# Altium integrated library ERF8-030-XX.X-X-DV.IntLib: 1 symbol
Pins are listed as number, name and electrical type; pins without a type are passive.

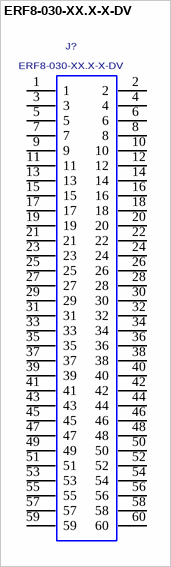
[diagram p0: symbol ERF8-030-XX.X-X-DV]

## ERF8-030-XX.X-X-DV
designator J?
0.8mm Edge Rate Socket Assembly, Double Vertical Row, 30 Positions Per Row.; MANUFACTURER: SAMTEC
footprint ERF8-030-XX.X-X-DV
pins: 1, 2, 3, 4, 5, 6, 7, 8, 9, 10, 11, 12, 13, 14, 15, 16, 17, 18, 19, 20, 21, 22, 23, 24, 25, 26, 27, 28, 29, 30, 31, 32, 33, 34, 35, 36, 37, 38, 39, 40, 41, 42, 43, 44, 45, 46, 47, 48, 49, 50, 51, 52, 53, 54, 55, 56, 57, 58, 59, 60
